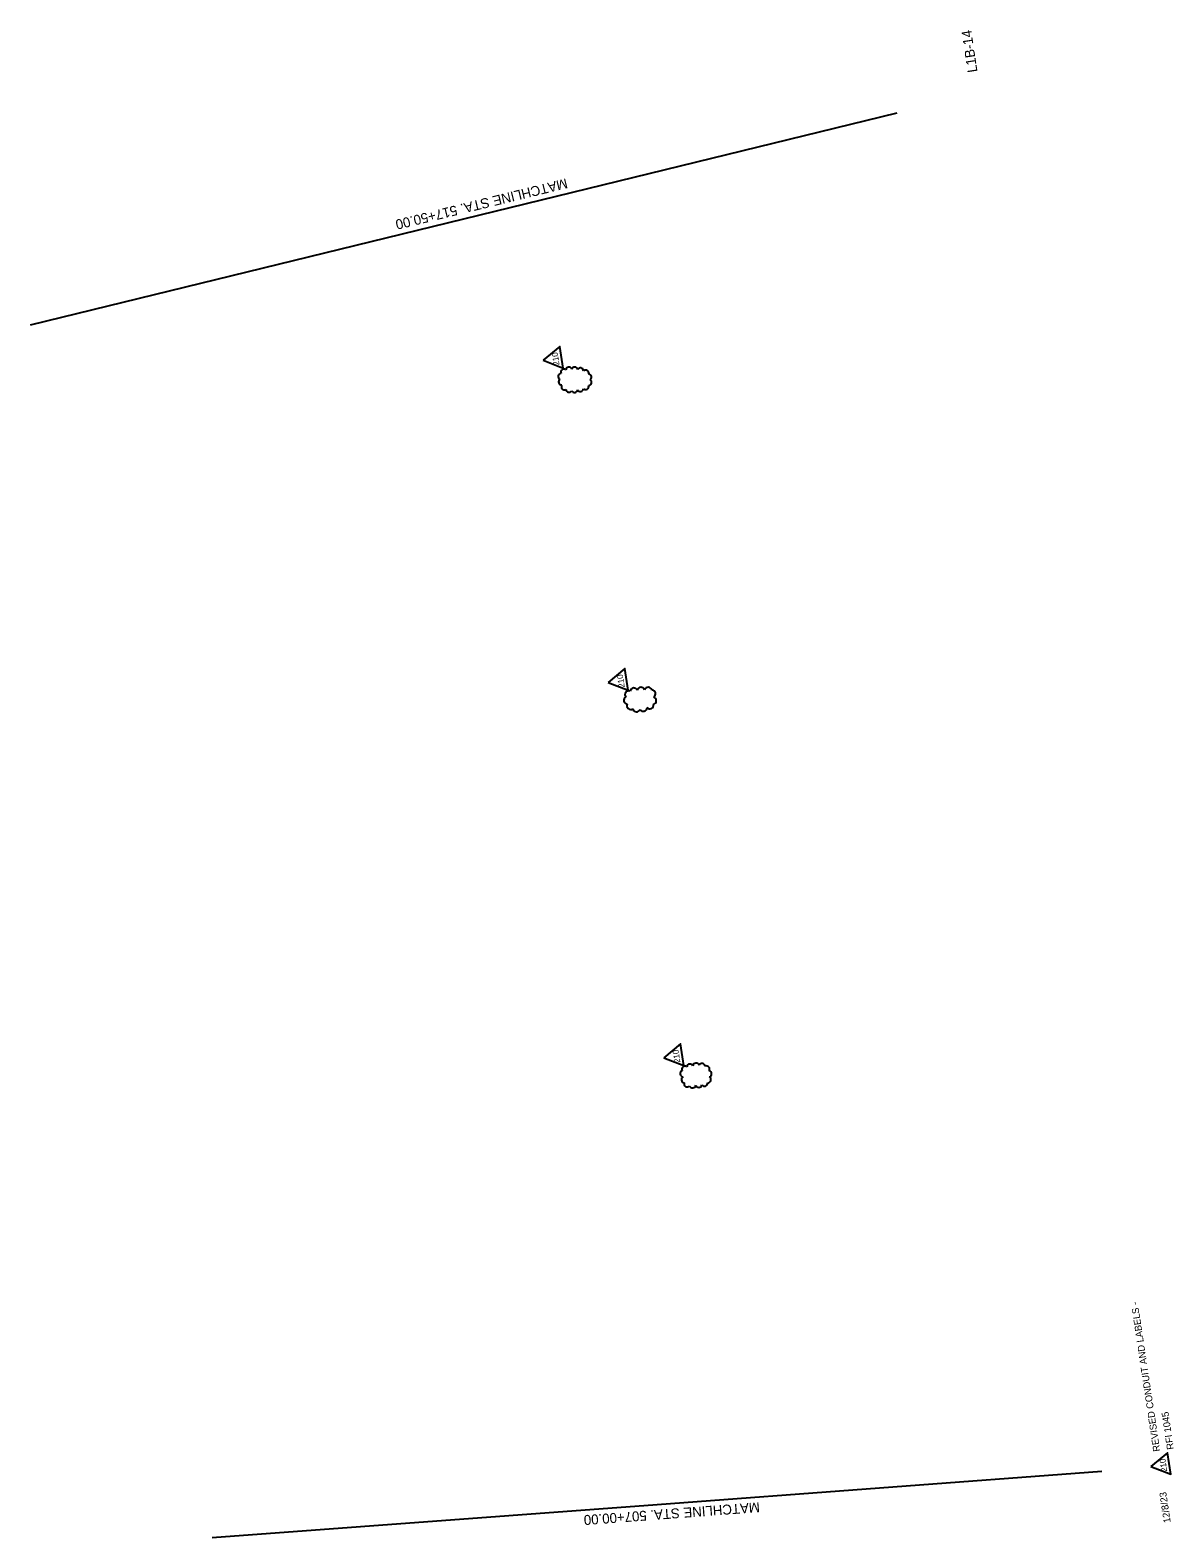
# Model space of a CAD drawing. Extents: x 930661 to 931584, y 626817 to 628033.
import ezdxf

# ---------------------------------------------------------------- set-up
doc = ezdxf.new("R2010")
doc.units = 0
for name, color, linetype in [('Cloud_dp', 7, 'Continuous'), ('MatchLines_dp', 7, 'Continuous'), ('TextMinor', 7, 'Continuous'), ('TextShtNo', 7, 'Continuous')]:
    doc.layers.add(name, color=color, linetype=linetype)

msp = doc.modelspace()

# ---------------------------------------------------------------- linework, layer by layer
at = {"layer": 'Cloud_dp'}
for points in [[(931074.7, 627766.3), (931090.8, 627760), (931088.2, 627777.5)], [(931127.2, 627506.5), (931143.4, 627500.2), (931140.7, 627517.6)], [(931172.1, 627203.8), (931188.3, 627197.6), (931185.7, 627215)], [(931565.1, 626874), (931581.2, 626867.8), (931578.6, 626885.2)]]:
    msp.add_lwpolyline(points, close=True, dxfattribs=at)
for centre, radius, start, end in [((931089.5, 627753.2), 2.54, 97.1564, 242.1564), ((931091.6, 627756.6), 2.54, 55.5014, 200.5014), ((931095.5, 627758.2), 2.54, 23.4737, 168.4737), ((931100.2, 627758.3), 2.54, 13.5174, 158.5174), ((931104.8, 627757.6), 2.54, 4.4267, 149.4267), ((931109.1, 627755.9), 2.54, 346.4571, 131.4571), ((931111.3, 627752.7), 2.54, 300.9098, 85.9098), ((931089.8, 627748.9), 2.54, 125.8069, 270.8069), ((931092, 627745), 2.54, 148.6783, 293.6783), ((931095.6, 627743), 2.54, 185.7344, 330.7344), ((931100.1, 627742.8), 2.54, 206.0657, 351.0657), ((931104.8, 627743.6), 2.54, 207.7987, 352.7987), ((931109, 627745.2), 2.54, 229.4623, 14.4623), ((931111.3, 627748.4), 2.54, 273.0114, 58.0114), ((931143.9, 627496.5), 3.09, 70.8468, 215.8468), ((931148, 627498.9), 3.09, 25.6778, 170.6778), ((931153.7, 627499.5), 3.09, 20.7295, 165.7295), ((931159.5, 627499.5), 3.09, 14.4662, 159.4662), ((931162.4, 627497.2), 3.09, 302.6667, 87.6667), ((931142.9, 627492), 3.09, 119.0822, 264.0822), ((931145.4, 627487.7), 3.09, 156.758, 301.758), ((931160.8, 627488.3), 3.09, 223.4286, 8.4286), ((931163, 627491.7), 3.09, 285.7198, 70.7198), ((931150.1, 627485.8), 3.09, 192.0225, 337.0225), ((931155.5, 627486.3), 3.09, 213.401, 358.401), ((931189.3, 627194.3), 2.61, 57.5198, 202.5198), ((931193.3, 627196.1), 2.61, 26.0657, 171.0657), ((931198.2, 627196.8), 2.61, 24.1288, 169.1288), ((931202.9, 627196.6), 2.61, 7.1682, 152.1682), ((931206.5, 627194.5), 2.61, 328.9192, 113.9192), ((931188, 627191), 2.61, 116.0657, 261.0657), ((931188.9, 627186.1), 2.61, 118.872, 263.872), ((931191.1, 627182.9), 2.61, 166.2519, 311.2519), ((931204.9, 627183.4), 2.61, 216.6962, 1.6962), ((931207.5, 627186.1), 2.61, 270.647, 55.647), ((931208.1, 627190.7), 2.61, 289.4244, 74.4244), ((931195.3, 627182), 2.61, 204.2069, 349.2069), ((931200.3, 627182.4), 2.61, 201.1639, 346.1639)]:
    msp.add_arc(centre, radius, start, end, dxfattribs=at)
at = {"layer": 'MatchLines_dp'}
for points in [[(931360.2, 627965.5), (931010.5, 627880.1), (930660.8, 627794.7)], [(931525.7, 626869.9), (931166.7, 626843.2), (930807.7, 626816.5)]]:
    msp.add_lwpolyline(points, dxfattribs=at)

# ---------------------------------------------------------------- texts
at = {"layer": 'Cloud_dp'}
for p in [(931088, 627762.4), (931140.6, 627502.6), (931185.5, 627199.9), (931578.4, 626870.1)]:
    msp.add_text('210', height=4.8, rotation=98.5657, dxfattribs=at).set_placement(p)
at = {"layer": 'MatchLines_dp'}
for s, rotation, p in [('MATCHLINE STA. 517+50.00', 193.7289, (931093.3, 627913.1)), ('MATCHLINE STA. 507+00.00', 184.2492, (931249.3, 626845.3))]:
    msp.add_text(s, height=8, rotation=rotation, dxfattribs=at).set_placement(p)
at = {"layer": 'TextMinor'}
for s, p in [('REVISED CONDUIT AND LABELS - ', (931572.7, 626886.5)), ('RFI 1045', (931583.8, 626888.1)), ('12/8/23', (931581.2, 626829.1))]:
    msp.add_text(s, height=5.6, rotation=98.5657, dxfattribs=at).set_placement(p)
at = {"layer": 'TextShtNo'}
msp.add_text('L1B-14', height=8, rotation=98.5657, dxfattribs=at).set_placement((931425.3, 627999))

doc.saveas('drawing.dxf')
